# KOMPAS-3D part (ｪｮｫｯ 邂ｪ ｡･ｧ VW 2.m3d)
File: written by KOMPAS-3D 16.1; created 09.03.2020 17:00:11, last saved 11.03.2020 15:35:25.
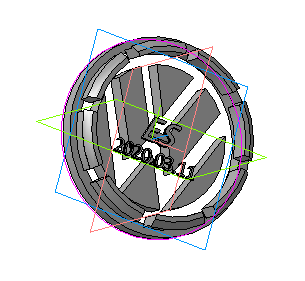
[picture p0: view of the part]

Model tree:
1. Эскиз:1
2. Операция выдавливания:1
     Расстояние 1 = 5.3
3. Эскиз:3
4. Вырезать элемент выдавливания:1
     Расстояние 1 = 5.3
5. Эскиз:7
6. Операция выдавливания:4
     Расстояние 1 = 3
7. Эскиз:8
8. Операция выдавливания:5
     Расстояние 1 = 4
9. Фаска:3
     Угол = 45; Длина 1 = 2; Длина 2 = 2
10. Фаска:4
     Угол = 26.5651; Длина 1 = 2; Длина 2 = 1
11. Эскиз:9
12. Вырезать элемент выдавливания:2
     Расстояние 1 = 7
13. Эскиз:10
14. Операция выдавливания:6
     Расстояние 1 = 1
15. Фаска:6
     Угол = 45; Длина 1 = 1; Длина 2 = 1

Referenced files in D:\3d\: volkswagen-folksvagen.jpg
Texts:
  Слой 1
  Слой 2
  Hot Mustard BTN
  Segoe UI Semibold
